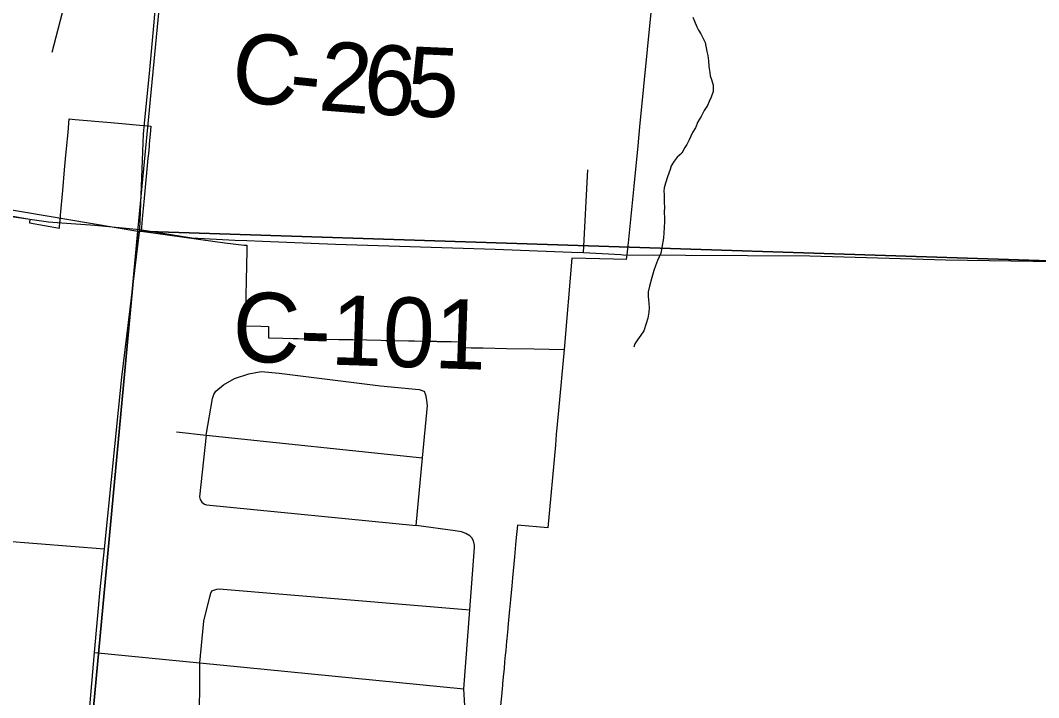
# Model space of a CAD drawing. Extents: x 0 to 34, y 0 to 22.
# Drawn here: x 4.4325 to 4.8475, y 20.1554 to 20.4315 of the extents above; entities that cross this region are included whole.
import ezdxf

# ---------------------------------------------------------------- set-up
doc = ezdxf.new("R2010")
doc.units = 0
for name, color, linetype in [('GM_X_City_Street', 7, 'Continuous'), ('GM_X_Corporation', 7, 'Continuous'), ('GM_X_County_Road', 7, 'Continuous'), ('GM_X_County_Road_Text', 7, 'Continuous'), ('GM_X_Minor_River', 7, 'Continuous'), ('GM_X_Section', 7, 'Continuous'), ('GM_X_State_Shield', 7, 'Continuous'), ('GM_X_Township_Road', 7, 'Continuous')]:
    doc.layers.add(name, color=color, linetype=linetype)

msp = doc.modelspace()

# ---------------------------------------------------------------- linework, layer by layer
at = {"layer": 'GM_X_City_Street'}
for points in [[(4.68957, 20.43597), (4.68489, 20.388), (4.68413, 20.38034), (4.6825, 20.36389), (4.68142, 20.35302), (4.6802, 20.34073), (4.68011, 20.33981), (4.67983, 20.33695), (4.67937, 20.33406), (4.67424, 20.33417), (4.65726, 20.33452), (4.65415, 20.29729), (4.65185, 20.27252), (4.65093, 20.26261), (4.65055, 20.25837), (4.64742, 20.22457), (4.63505, 20.22574), (4.63445, 20.21927), (4.63384, 20.21276), (4.63332, 20.20714), (4.63305, 20.20424), (4.63275, 20.20095), (4.63222, 20.19532), (4.63184, 20.1912), (4.63174, 20.19003), (4.63118, 20.18407), (4.63112, 20.18342), (4.63074, 20.17933), (4.63065, 20.17838), (4.63031, 20.17465), (4.63013, 20.17273), (4.62987, 20.16996), (4.62962, 20.16721), (4.62942, 20.1651), (4.62906, 20.16125), (4.62899, 20.16046), (4.62857, 20.15599), (4.62811, 20.151)], [(4.50828, 20.26242), (4.51083, 20.27732), (4.51139, 20.27901), (4.51222, 20.28034), (4.51531, 20.28295), (4.51973, 20.28553), (4.52565, 20.28733), (4.53061, 20.28838), (4.53801, 20.28768), (4.57933, 20.28257), (4.59507, 20.28095), (4.59631, 20.28058), (4.59715, 20.28016)], [(4.61418, 20.1428), (4.61322, 20.15906), (4.61568, 20.19115), (4.61764, 20.21664), (4.61756, 20.21754), (4.61712, 20.21931), (4.61643, 20.22058), (4.61563, 20.22143), (4.6141, 20.22237), (4.61224, 20.22301), (4.60976, 20.22336), (4.59386, 20.22562), (4.59641, 20.25315), (4.59837, 20.27443), (4.59817, 20.27652), (4.59784, 20.27834), (4.59763, 20.27908), (4.59715, 20.28016)], [(4.49614, 20.2637), (4.50828, 20.26242), (4.59641, 20.25315)], [(4.50828, 20.26242), (4.50553, 20.23728), (4.5058, 20.23618), (4.50639, 20.23513), (4.50749, 20.23433), (4.50832, 20.234), (4.59386, 20.22562)], [(4.41155, 20.22051), (4.42558, 20.21936), (4.46672, 20.21601)], [(4.44298, 19.95179), (4.48124, 19.94839), (4.48202, 19.94852), (4.48275, 19.9488), (4.48317, 19.94912), (4.48358, 19.94944), (4.48394, 19.95022), (4.48431, 19.95122), (4.49345, 20.0208), (4.50549, 20.14115), (4.50557, 20.16958), (4.50726, 20.18665), (4.50968, 20.19657), (4.51012, 20.19807), (4.51053, 20.19896)], [(4.51053, 20.19896), (4.51252, 20.19964), (4.5138, 20.19975), (4.5151, 20.19964), (4.61568, 20.19115)], [(4.46275, 20.17377), (4.50557, 20.16958), (4.61322, 20.15906)]]:
    msp.add_lwpolyline(points, dxfattribs=at)
at = {"layer": 'GM_X_Corporation'}
msp.add_lwpolyline([(4.40387, 20.35625), (4.43474, 20.35069), (4.43634, 20.35049), (4.4362, 20.349), (4.44839, 20.34681), (4.44863, 20.34942), (4.44864, 20.3496), (4.44886, 20.352), (4.44977, 20.36205), (4.45053, 20.37054), (4.45107, 20.37653), (4.4513, 20.37903), (4.45167, 20.38321), (4.45191, 20.38577), (4.4524, 20.39127), (4.45476, 20.39106), (4.46935, 20.38978), (4.48572, 20.38834), (4.48555, 20.38657), (4.48501, 20.38096), (4.48493, 20.38014), (4.48465, 20.3772), (4.48447, 20.37528), (4.48281, 20.35754), (4.48228, 20.35205), (4.48197, 20.34877), (4.48167, 20.34549), (4.50419, 20.34247), (4.50606, 20.34219), (4.51584, 20.34078), (4.52374, 20.33983), (4.52479, 20.33983), (4.52473, 20.33769), (4.52405, 20.307), (4.5305, 20.30681), (4.53365, 20.30664), (4.5336, 20.30206), (4.53948, 20.30193), (4.54363, 20.30184), (4.54517, 20.3018), (4.54571, 20.30179), (4.55087, 20.30168), (4.55628, 20.30157), (4.55657, 20.30156), (4.55713, 20.30155), (4.56226, 20.30144), (4.56674, 20.30135), (4.568, 20.30133), (4.57365, 20.30121), (4.5737, 20.30121), (4.57935, 20.30109), (4.5815, 20.30105), (4.58505, 20.30098), (4.59075, 20.30087), (4.59318, 20.30082), (4.59648, 20.30075), (4.60199, 20.30065), (4.60238, 20.30064), (4.60802, 20.30054), (4.61185, 20.30046), (4.61163, 20.29811), (4.6162, 20.29802), (4.6211, 20.29793), (4.63057, 20.29775), (4.64193, 20.29753), (4.65415, 20.29729), (4.65185, 20.27252), (4.65093, 20.26261), (4.65055, 20.25837), (4.64742, 20.22457), (4.63505, 20.22574), (4.63445, 20.21927), (4.63384, 20.21276), (4.63332, 20.20714), (4.63305, 20.20424), (4.63275, 20.20095), (4.63222, 20.19532), (4.63184, 20.1912), (4.63174, 20.19003), (4.63118, 20.18407), (4.63112, 20.18342), (4.63074, 20.17933), (4.63065, 20.17838), (4.63031, 20.17465), (4.63013, 20.17273), (4.62987, 20.16996), (4.62962, 20.16721), (4.62942, 20.1651), (4.62906, 20.16125), (4.62899, 20.16046), (4.62857, 20.15599), (4.62811, 20.151)], dxfattribs=at)
at = {"layer": 'GM_X_County_Road'}
msp.add_line((4.5199, 20.34187), (4.52483, 20.3417), dxfattribs=at)
for points in [[(4.48311, 20.38942), (4.48519, 20.41131), (4.48897, 20.45191), (4.49414, 20.50733), (4.49918, 20.55357), (4.50515, 20.60819)], [(4.48118, 20.34623), (4.48269, 20.38505), (4.48311, 20.38942)], [(4.32458, 20.3676), (4.36675, 20.36218), (4.4072, 20.35519), (4.4289, 20.35149), (4.44394, 20.34936), (4.44933, 20.34898)], [(4.43623, 19.87589), (4.44298, 19.95179), (4.45226, 20.02441), (4.45601, 20.09823), (4.4605, 20.14853), (4.46275, 20.17377), (4.46505, 20.19955), (4.46672, 20.21601), (4.47382, 20.28606), (4.48118, 20.34623)], [(4.44933, 20.34898), (4.46281, 20.34804), (4.48118, 20.34623)], [(4.48118, 20.34623), (4.50239, 20.34286), (4.5199, 20.34187)], [(4.52483, 20.3417), (4.53124, 20.34146), (4.56092, 20.34031), (4.62594, 20.33826), (4.65715, 20.33699)], [(4.65715, 20.33699), (4.66203, 20.3368), (4.67721, 20.33601)], [(4.67721, 20.33601), (4.67822, 20.33596), (4.75426, 20.33555), (4.80974, 20.33382), (4.93354, 20.33201)]]:
    msp.add_lwpolyline(points, dxfattribs=at)
at = {"layer": 'GM_X_Minor_River'}
msp.add_lwpolyline([(4.70661, 20.43272), (4.70731, 20.43117), (4.70817, 20.42886), (4.70888, 20.4275), (4.70977, 20.42594), (4.71154, 20.42245), (4.71234, 20.4188), (4.71266, 20.41708), (4.71295, 20.41497), (4.71305, 20.41269), (4.71352, 20.4102), (4.71366, 20.40886), (4.71416, 20.40732), (4.71483, 20.40501), (4.71492, 20.40253), (4.71406, 20.4001), (4.71322, 20.39842), (4.71258, 20.39673), (4.71116, 20.3947), (4.70991, 20.39227), (4.70867, 20.39004), (4.70762, 20.38761), (4.70639, 20.38576), (4.70512, 20.38277), (4.70409, 20.3809), (4.70327, 20.37961), (4.70203, 20.37737), (4.70024, 20.37573), (4.69903, 20.37407), (4.69781, 20.37222), (4.69736, 20.37071), (4.69628, 20.36771), (4.69541, 20.36509), (4.69495, 20.3632), (4.6947, 20.36188), (4.69484, 20.36055), (4.69495, 20.35864), (4.69489, 20.35712), (4.69501, 20.3554), (4.69491, 20.35313), (4.69502, 20.35103), (4.69496, 20.34951), (4.69485, 20.34704), (4.69467, 20.34268), (4.69395, 20.3389), (4.69347, 20.33664), (4.6922, 20.33365), (4.69134, 20.3314), (4.69069, 20.32952), (4.68981, 20.32671), (4.6889, 20.32313), (4.68842, 20.32087), (4.68834, 20.31897), (4.68848, 20.31763), (4.68861, 20.31611), (4.68873, 20.31439), (4.68865, 20.31249), (4.68817, 20.31004), (4.68751, 20.30797), (4.68662, 20.30497), (4.68539, 20.30311), (4.68398, 20.30127), (4.68296, 20.2996), (4.68252, 20.29828)], dxfattribs=at)
at = {"layer": 'GM_X_Section'}
for points in [[(4.52837, 20.84401), (5.04007, 20.86758), (4.98132, 20.32923), (4.48038, 20.34556)], [(4.00293, 20.42622), (4.48038, 20.34556), (4.43689, 19.87849), (3.95103, 19.92358)], [(4.48038, 20.34556), (4.98132, 20.32923), (4.93085, 19.82538), (4.43689, 19.87849)]]:
    msp.add_lwpolyline(points, close=True, dxfattribs=at)
at = {"layer": 'GM_X_State_Shield'}
msp.add_lwpolyline([(4.22367, 20.9), (4.05097, 20.9), (4.00293, 20.42622), (4.48038, 20.34556), (4.52837, 20.84401)], close=True, dxfattribs=at)
at = {"layer": 'GM_X_Township_Road'}
for p, q in [((4.45594, 20.45945), (4.44525, 20.41829)), ((4.66203, 20.3368), (4.66379, 20.37048))]:
    msp.add_line(p, q, dxfattribs=at)

# ---------------------------------------------------------------- texts
at = {"layer": 'GM_X_County_Road_Text'}
for s, height, rotation, p in [('C', 0.02841, 352.7523, (4.51736, 20.39917)), ('2', 0.02841, 355.429, (4.55356, 20.39489)), ('6', 0.02841, 357.1052, (4.57191, 20.39343)), ('5', 0.02841, 357.4865, (4.58959, 20.39254)), ('-', 0.02841, 354.1204, (4.54125, 20.39615)), ('C-101', 0.028409, 358.0724, (4.5186, 20.29254))]:
    msp.add_text(s, height=height, rotation=rotation, dxfattribs=at).set_placement(p)

doc.saveas('drawing.dxf')
